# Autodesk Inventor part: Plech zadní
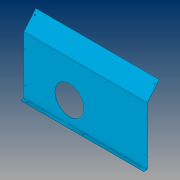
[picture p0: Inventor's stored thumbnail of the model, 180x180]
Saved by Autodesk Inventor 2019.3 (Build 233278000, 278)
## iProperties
Created: 2019-02
Part Number: Plech zadní
Material: Ocel, měkká, svařovaná
Document SubType Name: Plech
Designer: B-hon
Density: 7.85 g/cm^3
Sheet Metal Rule: Výchozí_mm
Appearance: Nebeská modrá – střední
Mass: 4648.15 g
Surface Area: 5981.43 cm^2
Volume: 592.12 cm^3
Flat Pattern Width: 45.2351 cm
Flat Pattern Length: 70.2 cm
Flat Pattern Area: 3175.5 cm^2
Sheet Metal Width: 452,351 mm
Sheet Metal Length: 702,000 mm
Sheet Metal Area: 317550,227 mm^2
Author: B-hon
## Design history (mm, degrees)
node "Plocha1"
  sketch "Náčrt1"
    geometry: L1 (-351, 165.364)-(351, 165.364); L2 (351, 165.364)-(351, -165.364); L3 (351, -165.364)-(-351, -165.364); L4 (-351, -165.364)-(-351, 165.364); L5 (-351, 165.364)-(351, -165.364); L6 (351, 165.364)-(-351, -165.364); 1 further point
    constraints: 12 end point, 2 midpoint, 2 parallel, 1 horizontal, 1 perpendicular
    dimensions: "d0" = 702 distance of L2.end L3.end; "d1" = 330.728 distance of L1.end L2.end
node "Obruba1"
node "Obruba2"
sketch "Náčrt4"
  geometry: L1 (-351, -161.364)-(-351, 163.908) reference; L2 (-351, -165.364)-(351, -165.364) reference; C1 r 82.5 at (-92.2, -42.864); 1 further point
  constraints: 1 centre point
  dimensions: "d23" = 258.8 distance from line of C1.centre L1; "d24" = 122.5 distance from line of L2 C1.centre; "d25" = 165 diameter of C1
extrude "Vysunutí1" cut sketch "Náčrt4" distance "d26" = 10; taper "d27" = 0 deg
sketch "Náčrt5"
  geometry: L1 (702, 16)-(702, 0) reference; L2 (0, 0)-(702, 0) reference; 2 further points
  dimensions: "d28" = 36 distance from line of L1 point (666, 8); "d29" = 8 distance from line of L2 point (666, 8)
hole "Díra1" sketch "Náčrt5" at (666, 8) diameter "d30" = 6.5; stored, may be unused: countersink angle "d34" = 90 deg, drill point angle "d36" = 118 deg; dims "d31" = 6, "d32" = 4, "d33" = 2, "d35" = 2 (= Tloušťka)
pattern_linear "Obdélníkové pole1" dims "d39" = 318
sketch "Náčrt6"
  geometry: L1 (351, 163.908)-(351, -161.364) reference; L2 (-351, -165.364)-(351, -165.364) reference; 2 further points
  dimensions: "d40" = 10 distance from line of L1 point (341, -95.364); "d41" = 70 distance from line of L2 point (341, -95.364)
hole "Díra2" sketch "Náčrt6" at (341, -95.364) diameter "d42" = 6.5; stored, may be unused: countersink angle "d46" = 90 deg, drill point angle "d48" = 118 deg; dims "d43" = 6, "d44" = 4, "d45" = 2, "d47" = 2 (= Tloušťka)
pattern_linear "Obdélníkové pole2" dims "d51" = 682, "d54" = 180
sketch "Náčrt7"
  geometry: L1 (702, 0)-(702, -104.544) reference; L2 (0, 0)-(702, 0) reference; 2 further points
  dimensions: "d55" = 10 distance from line of L1 point (692, -25); "d56" = 25 distance from line of L2 point (692, -25)
hole "Díra3" sketch "Náčrt7" at (692, -25) diameter "d57" = 6.5; stored, may be unused: countersink angle "d61" = 90 deg, drill point angle "d63" = 118 deg; dims "d58" = 6, "d59" = 4, "d60" = 2, "d62" = 2 (= Tloušťka)
pattern_linear "Obdélníkové pole3" dims "d66" = 682
node "Těleso1"
feature "Deska1" dims "d2" = 2 (= Tloušťka)
sketch "Náčrt2"
  geometry: L1 through (-351, 0) direction (1, -1.25e-48); L2 through (0, 10) direction (0, 1); L3 (0, 20)-(-702, 20); L4 (-702, 20)-(-702, 0)
  constraints: 6 end point, 1 horizontal, 1 perpendicular, 1 vertical
feature "Deska2" dims "d2" = 2 (= Tloušťka), "d3" = 2 (= ŠířkaVýštipu), "d4" = 1 (= HloubkaVýštipu), "d5" = 4 (= MinimálníZbytek), "d6" = 2 (= PřechodovýPoloměr), "d7" = 20, "d8" = 90 deg, "d9" = 2 (= PoloměrOhybu), "d10" = 8 (= VelikostRohovéhoVýštipu), "d11" = 2 (= VelikostMezery), "d12" = 2 (= VelikostJacobihoPoloměru), "MezeraVystřižení" = 0.01
feature "Ohyb1" dims "d2" = 2 (= Tloušťka), "d3" = 2 (= ŠířkaVýštipu), "d4" = 1 (= HloubkaVýštipu), "d5" = 4 (= MinimálníZbytek), "d6" = 2 (= PřechodovýPoloměr), "d7" = 20, "d8" = 90 deg, "d9" = 2 (= PoloměrOhybu), "MezeraVystřižení" = 0.01
feature "Roh1" dims "d7" = 20, "d8" = 90 deg, "d10" = 8 (= VelikostRohovéhoVýštipu), "d11" = 2 (= VelikostMezery), "d12" = 2 (= VelikostJacobihoPoloměru)
sketch "Náčrt3"
  geometry: L1 through (351, 0) direction (-1, 0); L2 through (0, -53) direction (0, -1); L3 (0, -106)-(702, -106); L4 (702, -106)-(702, 0)
  constraints: 6 end point, 1 horizontal, 1 perpendicular, 1 vertical
feature "Deska3" dims "d2" = 2 (= Tloušťka), "d13" = 2 (= ŠířkaVýštipu), "d14" = 1 (= HloubkaVýštipu), "d15" = 4 (= MinimálníZbytek), "d16" = 2 (= PřechodovýPoloměr), "d17" = 106, "d18" = 40 deg, "d19" = 2 (= PoloměrOhybu), "d20" = 8 (= VelikostRohovéhoVýštipu), "d21" = 2 (= VelikostMezery), "d22" = 2 (= VelikostJacobihoPoloměru), "MezeraVystřižení" = 0.01
feature "Ohyb2" dims "d2" = 2 (= Tloušťka), "d13" = 2 (= ŠířkaVýštipu), "d14" = 1 (= HloubkaVýštipu), "d15" = 4 (= MinimálníZbytek), "d16" = 2 (= PřechodovýPoloměr), "d17" = 106, "d18" = 40 deg, "d19" = 2 (= PoloměrOhybu), "MezeraVystřižení" = 0.01
feature "Roh2" dims "d17" = 106, "d18" = 40 deg, "d20" = 8 (= VelikostRohovéhoVýštipu), "d21" = 2 (= VelikostMezery), "d22" = 2 (= VelikostJacobihoPoloměru)
feature "Definice1"
other parameters: "Tloušťka" = 2, "KSoučinitel" = 4.4, "PoloměrOhybu" = 2 (= Tloušťka), "ŠířkaVýštipu" = 2 (= Tloušťka), "HloubkaVýštipu" = 1 (= 0.5 x Tloušťka), "VelikostRohovéhoVýštipu" = 8 (= 4 x Tloušťka), "MinimálníZbytek" = 4 (= 2 x Tloušťka), "PřechodovýPoloměr" = 2 (= PoloměrOhybu), "VelikostJacobihoPoloměru" = 2 (= PoloměrOhybu), "VelikostMezery" = 2 (= Tloušťka), "HloubkaVýštipu" = 1, "MinimálníZbytek" = 4, "PoloměrOhybu" = 2, "PřechodovýPoloměr" = 2, "Tloušťka" = 2, "VelikostJacobihoPoloměru" = 2, "VelikostMezery" = 2, "VelikostRohovéhoVýštipu" = 8, "ŠířkaVýštipu" = 2
